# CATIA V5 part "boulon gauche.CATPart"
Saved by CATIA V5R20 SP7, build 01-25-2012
Part number: boulon gauche
Bounding box of the stored display mesh (mm): x 7.86 to 16.96, y 18.5 to 27.5, z 39.221 to 41.221
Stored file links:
  F:\Travaux\Modélisations\CFAO_2011\CFAO_2011_MMS\CFAO_2011_MMS_DONE\CFAO_2011_MMS_jboiteux\Catia\boulon gauche.CATPart
  U:\finthinkmotion\stepper.CATProduct
  F:\Travaux\Modélisations\CFAO_2011\CFAO_2011_MMS\CFAO_2011_MMS_DONE\CFAO_2011_MMS_jboiteux\Catia\vis gauche.CATPart
  F:\Travaux\Modélisations\CFAO_2011\CFAO_2011_MMS\CFAO_2011_MMS_DONE\CFAO_2011_MMS_jboiteux\Catia\bati.CATPart
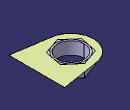
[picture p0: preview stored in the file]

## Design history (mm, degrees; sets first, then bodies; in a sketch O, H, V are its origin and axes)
Parameters
  rayontube = 9 mm {= External.royontubebati}
External parameters (linked from other documents)
  External.royontubebati = 9 mm
Set1
  DatumSurface1: linked copy from another document
  DatumSurface2: linked copy from another document
  Point1: linked copy from another document
Body1 (main body)
  Sketch1 on DatumSurface1, origin (0, 0, 41.221), H (1, 0, 0), V (0, 1, 0)
    projected circle E1 centre (11.46, 23) radius 2.15 from face of DatumSurface2
    point P1 (11.46, 23)
    point P2 (9.3428, 24.8449)
    point P3 (8.8037, 22.0889)
    point P4 (10.9209, 20.244)
    point P5 (13.5772, 21.1551)
    point P6 (14.1163, 23.9111)
    point P7 (11.9991, 25.756)
    point P8 (9.0732, 23.4669)
    line L1 (9.3428, 24.8449) -> (8.8037, 22.0889)
    line L2 (8.8037, 22.0889) -> (10.9209, 20.244)
    line L3 (10.9209, 20.244) -> (13.5772, 21.1551)
    line L4 (13.5772, 21.1551) -> (14.1163, 23.9111)
    line L5 (14.1163, 23.9111) -> (11.9991, 25.756)
    line L6 (11.9991, 25.756) -> (9.3428, 24.8449)
    construction line L7 (11.46, 23) -> (9.0732, 23.4669)
    construction circle A1 centre (11.46, 23) radius 2.8082
    construction arc A2 centre (14.1163, 23.9111) radius 2.8082 from (13.5772, 21.1551) to (11.9991, 25.756) cw
    construction arc A3 centre (8.8037, 22.0889) radius 2.8082 from (10.9209, 20.244) to (9.3428, 24.8449) ccw
    reference projected point E2 (11.46, 23) from Point1
    distance L4 E2 = 2.432 {= rayontube *304/1125}
    coincidence: A1 P2, A1 P3, A1 P4, A1 P5, A1 P6, A1 P7, A2 P1, A3 P1
    midpoint: P8 L1
    parallelism: L1 L4
    concentricity: P1 E1
  Pad1: profile Sketch1, direction (0, 0, -1), length 2 {= rayontube /4.5}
